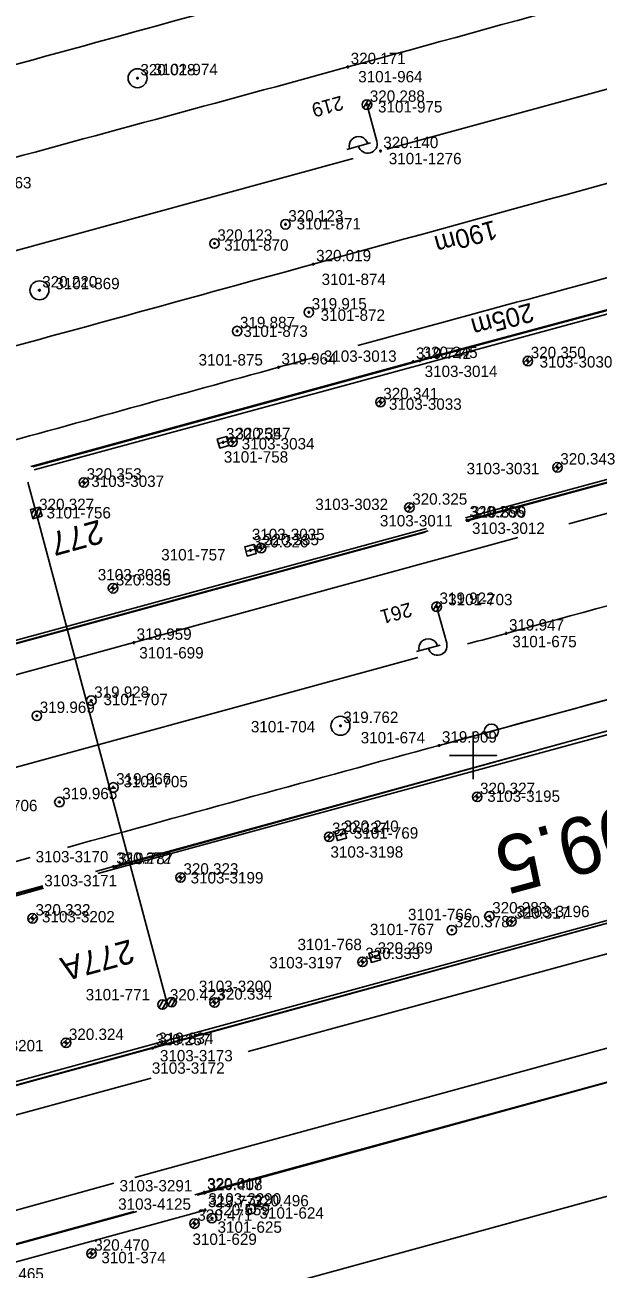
# Model space of a CAD drawing. Extents: x -821875 to -821475, y -1070280 to -1069975.
# Drawn here: x -821573.6 to -821543.4, y -1070227.1 to -1070161.5 of the extents above; entities that cross this region are included whole.
import ezdxf

# ---------------------------------------------------------------- set-up
doc = ezdxf.new("R2010")
doc.units = 0
for name, color, linetype in [('Vrstva 1', 7, 'Continuous'), ('Vrstva 11', 7, 'Continuous'), ('Vrstva 14', 7, 'Continuous'), ('Vrstva 17', 7, 'Continuous'), ('Vrstva 23', 7, 'Continuous'), ('Vrstva 25', 7, 'Continuous'), ('Vrstva 3', 7, 'Continuous'), ('Vrstva 36', 7, 'Continuous'), ('Vrstva 43', 7, 'Continuous'), ('Vrstva 60', 7, 'Continuous'), ('Vrstva 61', 7, 'Continuous'), ('Vrstva 7', 7, 'Continuous')]:
    doc.layers.add(name, color=color, linetype=linetype)

# ---------------------------------------------------------------- blocks, each defined once
blk = doc.blocks.new('BOD')
at = {"layer": 'Vrstva 3'}
for p, q in [((-0.15, 0), (0.15, 0)), ((0, -0.15), (0, 0.15))]:
    blk.add_line(p, q, dxfattribs=at)

msp = doc.modelspace()

# ---------------------------------------------------------------- linework, layer by layer
at = {"layer": 'Vrstva 1'}
for p, q in [((-821530.858, -1070161.578), (-821554.553, -1070168.036)), ((-821556.332, -1070168.522), (-821580.315, -1070175.074)), ((-821532.805, -1070194.296), (-821551.797, -1070199.466)), ((-821552.91, -1070194.831), (-821576.812, -1070201.363)), ((-821500, -1070203.666), (-821567.84, -1070222.249)), ((-821516.436, -1070203.219), (-821561.856, -1070215.603)), ((-821573.357, -1070205.377), (-821602.448, -1070213.353)), ((-821566.968, -1070216.997), (-821586.693, -1070222.375)), ((-821568.932, -1070222.548), (-821610.421, -1070233.913))]:
    msp.add_line(p, q, dxfattribs=at)
for points in [[(-821534.842, -1070185.015), (-821544.956, -1070187.779)], [(-821547.636, -1070188.511), (-821567.889, -1070194.046), (-821588.306, -1070199.621)], [(-821551.25, -1070200), (-821550, -1070200), (-821550, -1070198.75), (-821550, -1070200), (-821548.75, -1070200), (-821550, -1070200), (-821550, -1070201.25)]]:
    msp.add_lwpolyline(points, dxfattribs=at)
for points in [[(-821515.135, -1070116.801), (-821528.933, -1070119.148), (-821545.007, -1070122.191), (-821565.452, -1070126.847), (-821593.911, -1070134.524), (-821616.729, -1070140.773), (-821646.681, -1070148.977), (-821681.98, -1070158.691), (-821694.065, -1070162.076), (-821706.535, -1070165.88), (-821718.507, -1070169.937)], [(-821540.596, -1070125.428), (-821552.18, -1070128.307), (-821562.458, -1070130.974), (-821571.2, -1070133.262), (-821591.887, -1070138.848), (-821628.102, -1070148.713), (-821679.285, -1070162.663)], [(-821540.784, -1070127.42), (-821561.358, -1070134.748), (-821573.215, -1070138.464), (-821586.824, -1070142.326), (-821602.341, -1070146.553), (-821645.37, -1070158.257), (-821677.113, -1070166.912)], [(-821500, -1070129.211), (-821517.764, -1070133.43), (-821543.081, -1070140.233), (-821582.867, -1070151.05), (-821612.032, -1070158.997), (-821647.71, -1070168.745)], [(-821500, -1070134.157), (-821525.227, -1070140.424), (-821545.665, -1070145.962), (-821584.89, -1070156.649), (-821608.863, -1070163.173), (-821645.742, -1070173.228), (-821684.141, -1070183.689)], [(-821500, -1070139.002), (-821505.719, -1070140.359), (-821526.796, -1070145.75), (-821547.362, -1070151.333), (-821583.687, -1070161.245), (-821611.332, -1070168.765), (-821648.899, -1070179.006), (-821680.4, -1070187.609), (-821711.133, -1070195.974)], [(-821500, -1070143.947), (-821500.602, -1070144.082), (-821526.98, -1070150.62), (-821544.477, -1070155.432), (-821558.026, -1070159.151), (-821579.135, -1070164.951), (-821610.376, -1070173.463), (-821647.463, -1070183.595), (-821678.921, -1070192.191), (-821710.276, -1070200.761)], [(-821500, -1070148.817), (-821511.77, -1070151.622), (-821530.609, -1070156.564), (-821556.604, -1070163.701), (-821576.895, -1070169.217), (-821607.294, -1070177.525), (-821643.435, -1070187.343), (-821669.656, -1070194.488)], [(-821500, -1070158.612), (-821502.104, -1070159.113), (-821527.988, -1070165.772), (-821558.427, -1070174.094), (-821579.522, -1070179.891)], [(-821528.694, -1070170.935), (-821535.495, -1070172.784), (-821556.071, -1070178.381)], [(-821558.309, -1070178.995), (-821560.253, -1070179.53), (-821575.821, -1070183.825)], [(-821526.636, -1070187.658), (-821548.257, -1070193.56), (-821550.291, -1070194.116)], [(-821530.049, -1070193.542), (-821532.805, -1070194.296), (-821551.797, -1070199.466), (-821571.39, -1070204.838)], [(-821500, -1070224.932), (-821542.652, -1070236.59), (-821589.48, -1070249.332)]]:
    msp.add_spline(points, degree=3, dxfattribs=at)
at = {"layer": 'Vrstva 11'}
for p, q in [((-821573.469, -1070185.595), (-821573.029, -1070187.208)), ((-821573.108, -1070186.971), (-821573.273, -1070187.261)), ((-821572.854, -1070186.902), (-821573.202, -1070187.515)), ((-821573.029, -1070187.208), (-821566.136, -1070213.06)), ((-821572.784, -1070187.158), (-821572.947, -1070187.444)), ((-821566.328, -1070212.882), (-821566.562, -1070213.293)), ((-821565.843, -1070212.751), (-821566.079, -1070213.163)), ((-821565.687, -1070212.855), (-821565.909, -1070213.243)), ((-821566.171, -1070212.986), (-821566.393, -1070213.375))]:
    msp.add_line(p, q, dxfattribs=at)
msp.add_lwpolyline([(-821572.722, -1070187.383), (-821573.204, -1070187.515), (-821573.336, -1070187.033), (-821572.854, -1070186.901)], close=True, dxfattribs=at)
msp.add_lwpolyline([(-821572.722, -1070187.383), (-821573.204, -1070187.515), (-821573.336, -1070187.033), (-821572.854, -1070186.901), (-821572.722, -1070187.383)], dxfattribs=at)
for centre in [(-821566.377, -1070213.126), (-821566.377, -1070213.126), (-821565.895, -1070212.994), (-821565.895, -1070212.994)]:
    msp.add_circle(centre, 0.25, dxfattribs=at)
at = {"layer": 'Vrstva 14'}
for p, q in [((-821520.255, -1070170.56), (-821573.139, -1070184.936)), ((-821553.163, -1070179.239), (-821573.313, -1070184.766)), ((-821573.206, -1070184.774), (-821552.814, -1070179.193)), ((-821550.394, -1070187.471), (-821522.684, -1070179.932)), ((-821500, -1070187.198), (-821569.776, -1070206.214)), ((-821626.102, -1070208.071), (-821552.45, -1070188.031)), ((-821587.282, -1070220.776), (-821500, -1070196.987)), ((-821572.64, -1070206.994), (-821597.005, -1070213.634)), ((-821530.838, -1070213.903), (-821564.175, -1070223.021)), ((-821530.539, -1070213.83), (-821564.154, -1070223.059)), ((-821564.175, -1070223.021), (-821564.669, -1070223.157)), ((-821564.154, -1070223.059), (-821564.546, -1070223.166)), ((-821567.723, -1070224.034), (-821612.131, -1070236.166)), ((-821567.873, -1070224.036), (-821612.125, -1070236.188))]:
    msp.add_line(p, q, dxfattribs=at)
for points in [[(-821553.163, -1070179.239), (-821523.624, -1070171.317)], [(-821523.662, -1070171.348), (-821552.814, -1070179.193)], [(-821550.335, -1070187.597), (-821522.393, -1070180.046)], [(-821522.413, -1070180.061), (-821550.25, -1070187.611)], [(-821593.697, -1070199.421), (-821552.369, -1070188.152)], [(-821552.524, -1070188.23), (-821593.592, -1070199.416)], [(-821524.974, -1070193.772), (-821568.963, -1070205.855)], [(-821525.05, -1070193.765), (-821568.859, -1070205.873)], [(-821500, -1070197.101), (-821519.046, -1070202.296), (-821566.74, -1070215.352), (-821587.58, -1070221.064)], [(-821587.424, -1070221.035), (-821566.902, -1070215.424), (-821519.308, -1070202.358), (-821500, -1070197.087)], [(-821568.963, -1070205.855), (-821569.898, -1070206.112)], [(-821572.675, -1070206.874), (-821597.33, -1070213.642)], [(-821572.691, -1070206.915), (-821596.666, -1070213.434)]]:
    msp.add_lwpolyline(points, dxfattribs=at)
at = {"layer": 'Vrstva 17'}
msp.add_lwpolyline([(-821561.818, -1070228.402), (-821540.931, -1070222.686), (-821538.779, -1070230.644), (-821559.821, -1070236.162), (-821561.818, -1070228.402)], dxfattribs=at)
at = {"layer": 'Vrstva 23'}
msp.add_lwpolyline([(-821579.481, -1070228.171), (-821564.133, -1070223.955)], dxfattribs=at)
at = {"layer": 'Vrstva 25'}
for p, q in [((-821555.538, -1070165.445), (-821555.776, -1070165.86)), ((-821555.385, -1070165.554), (-821555.603, -1070165.935)), ((-821555.531, -1070165.928), (-821555.071, -1070167.616)), ((-821555.408, -1070167.708), (-821556.662, -1070168.05)), ((-821559.916, -1070171.997), (-821559.866, -1070171.997)), ((-821563.659, -1070173.009), (-821563.609, -1070173.009)), ((-821558.683, -1070176.633), (-821558.633, -1070176.633)), ((-821562.466, -1070177.622), (-821562.416, -1070177.622)), ((-821551.864, -1070191.911), (-821552.1, -1070192.326)), ((-821551.71, -1070192.02), (-821551.927, -1070192.401)), ((-821551.855, -1070192.394), (-821551.394, -1070194.082)), ((-821551.731, -1070194.174), (-821552.985, -1070194.517)), ((-821570.152, -1070197.103), (-821570.102, -1070197.103)), ((-821573.02, -1070197.904), (-821572.97, -1070197.904)), ((-821568.992, -1070201.676), (-821568.942, -1070201.676)), ((-821571.835, -1070202.448), (-821571.785, -1070202.448)), ((-821549.168, -1070208.47), (-821549.118, -1070208.47)), ((-821551.149, -1070209.203), (-821551.099, -1070209.203)), ((-821561.741, -1070223.912), (-821561.691, -1070223.912)), ((-821563.792, -1070224.385), (-821563.742, -1070224.385))]:
    msp.add_line(p, q, dxfattribs=at)
for centre in [(-821555.596, -1070165.687), (-821555.596, -1070165.687), (-821559.891, -1070171.997), (-821563.634, -1070173.009), (-821558.658, -1070176.633), (-821562.441, -1070177.622), (-821551.921, -1070192.153), (-821551.921, -1070192.153), (-821570.127, -1070197.103), (-821572.995, -1070197.904), (-821568.967, -1070201.676), (-821571.81, -1070202.448), (-821549.143, -1070208.47), (-821551.124, -1070209.203), (-821561.716, -1070223.912), (-821563.767, -1070224.385)]:
    msp.add_circle(centre, 0.25, dxfattribs=at)
for centre, start, end in [((-821556.037, -1070167.874), 14.53609, 195.94123), ((-821555.553, -1070167.748), 195.23866, 15.23866), ((-821552.359, -1070194.34), 14.59593, 196.00107), ((-821551.876, -1070194.214), 195.2985, 15.2985)]:
    msp.add_arc(centre, 0.5, start, end, dxfattribs=at)
at = {"layer": 'Vrstva 36'}
for p, q in [((-821547.344, -1070179.294), (-821547.02, -1070178.971)), ((-821547.214, -1070179.429), (-821546.886, -1070179.102)), ((-821555.116, -1070181.458), (-821554.794, -1070181.135)), ((-821554.986, -1070181.593), (-821554.659, -1070181.266)), ((-821562.91, -1070183.557), (-821562.588, -1070183.234)), ((-821562.78, -1070183.692), (-821562.453, -1070183.364)), ((-821545.784, -1070184.899), (-821545.462, -1070184.576)), ((-821545.654, -1070185.034), (-821545.327, -1070184.706)), ((-821570.752, -1070185.694), (-821570.43, -1070185.371)), ((-821570.622, -1070185.829), (-821570.295, -1070185.502)), ((-821553.59, -1070187.015), (-821553.268, -1070186.692)), ((-821553.46, -1070187.15), (-821553.133, -1070186.822)), ((-821561.408, -1070189.153), (-821561.086, -1070188.83)), ((-821561.278, -1070189.288), (-821560.951, -1070188.96)), ((-821569.212, -1070191.274), (-821568.89, -1070190.951)), ((-821569.082, -1070191.409), (-821568.755, -1070191.082)), ((-821550.016, -1070202.271), (-821549.692, -1070201.948)), ((-821549.886, -1070202.406), (-821549.558, -1070202.078)), ((-821557.82, -1070204.375), (-821557.498, -1070204.052)), ((-821557.69, -1070204.51), (-821557.363, -1070204.182)), ((-821565.652, -1070206.517), (-821565.33, -1070206.194)), ((-821565.522, -1070206.652), (-821565.195, -1070206.324)), ((-821573.452, -1070208.673), (-821573.128, -1070208.35)), ((-821573.322, -1070208.808), (-821572.994, -1070208.48)), ((-821548.216, -1070208.835), (-821547.892, -1070208.512)), ((-821548.086, -1070208.97), (-821547.758, -1070208.642)), ((-821556.064, -1070210.967), (-821555.74, -1070210.644)), ((-821555.934, -1070211.102), (-821555.606, -1070210.774)), ((-821563.862, -1070213.108), (-821563.538, -1070212.785)), ((-821563.732, -1070213.243), (-821563.404, -1070212.916)), ((-821571.69, -1070215.233), (-821571.368, -1070214.91)), ((-821571.56, -1070215.368), (-821571.233, -1070215.04)), ((-821564.918, -1070224.763), (-821564.594, -1070224.44)), ((-821564.788, -1070224.898), (-821564.46, -1070224.57)), ((-821570.352, -1070226.34), (-821570.03, -1070226.017)), ((-821570.222, -1070226.475), (-821569.895, -1070226.148))]:
    msp.add_line(p, q, dxfattribs=at)
for centre in [(-821547.113, -1070179.202), (-821554.886, -1070181.366), (-821562.68, -1070183.465), (-821545.554, -1070184.807), (-821570.522, -1070185.602), (-821553.36, -1070186.923), (-821561.178, -1070189.061), (-821568.982, -1070191.182), (-821549.785, -1070202.179), (-821557.59, -1070204.283), (-821565.422, -1070206.425), (-821573.221, -1070208.581), (-821547.985, -1070208.743), (-821555.833, -1070210.875), (-821563.631, -1070213.016), (-821571.46, -1070215.141), (-821564.687, -1070224.671), (-821570.122, -1070226.248)]:
    msp.add_circle(centre, 0.25, dxfattribs=at)
at = {"layer": 'Vrstva 43'}
for points in [[(-821562.936, -1070183.42), (-821562.87, -1070183.66), (-821563.351, -1070183.793), (-821563.484, -1070183.312), (-821563.003, -1070183.179), (-821562.936, -1070183.42), (-821563.418, -1070183.552)], [(-821561.495, -1070189.111), (-821561.429, -1070189.352), (-821561.911, -1070189.484), (-821562.043, -1070189.002), (-821561.561, -1070188.87), (-821561.495, -1070189.111), (-821561.977, -1070189.243)], [(-821556.734, -1070204.105), (-821556.668, -1070204.346), (-821557.15, -1070204.478), (-821557.282, -1070203.996), (-821556.8, -1070203.864), (-821556.734, -1070204.105), (-821557.216, -1070204.237)], [(-821554.941, -1070210.526), (-821554.875, -1070210.768), (-821555.358, -1070210.899), (-821555.489, -1070210.416), (-821555.006, -1070210.285), (-821554.941, -1070210.526), (-821555.423, -1070210.658)]]:
    msp.add_lwpolyline(points, dxfattribs=at)
for centre in [(-821567.69, -1070164.294), (-821572.863, -1070175.473), (-821556.993, -1070198.431)]:
    msp.add_circle(centre, 0.5, dxfattribs=at)
at = {"layer": 'Vrstva 7'}
msp.add_circle((-821549.036, -1070198.714), 0.375, dxfattribs=at)

# ---------------------------------------------------------------- block references
at = {"layer": 'Vrstva 60', "xscale": 0.5, "yscale": 0.5}
for p in [(-821556.604, -1070163.701), (-821567.69, -1070164.294), (-821555.596, -1070165.687), (-821554.885, -1070168.127), (-821559.891, -1070171.997), (-821563.634, -1070173.009), (-821558.427, -1070174.094), (-821572.863, -1070175.473), (-821558.658, -1070176.633), (-821562.441, -1070177.622), (-821560.253, -1070179.53), (-821553.163, -1070179.239), (-821552.814, -1070179.193), (-821547.113, -1070179.202), (-821554.886, -1070181.366), (-821563.177, -1070183.486), (-821562.68, -1070183.465), (-821545.554, -1070184.807), (-821570.522, -1070185.602), (-821573.029, -1070187.208), (-821553.36, -1070186.923), (-821550.335, -1070187.597), (-821550.25, -1070187.611), (-821561.736, -1070189.177), (-821561.178, -1070189.061), (-821568.982, -1070191.182), (-821551.921, -1070192.153), (-821548.257, -1070193.56), (-821567.889, -1070194.046), (-821570.127, -1070197.103), (-821572.995, -1070197.904), (-821556.993, -1070198.431), (-821551.797, -1070199.466), (-821568.967, -1070201.676), (-821571.81, -1070202.448), (-821549.785, -1070202.179), (-821557.59, -1070204.283), (-821556.975, -1070204.171), (-821568.963, -1070205.855), (-821568.859, -1070205.873), (-821565.422, -1070206.425), (-821573.221, -1070208.581), (-821549.143, -1070208.47), (-821547.985, -1070208.743), (-821551.124, -1070209.203), (-821555.833, -1070210.875), (-821555.182, -1070210.592), (-821563.631, -1070213.016), (-821566.136, -1070213.06), (-821571.46, -1070215.141), (-821566.902, -1070215.424), (-821566.74, -1070215.352), (-821564.175, -1070223.021), (-821564.154, -1070223.059), (-821564.133, -1070223.955), (-821561.716, -1070223.912), (-821564.687, -1070224.671), (-821563.767, -1070224.385), (-821570.122, -1070226.248)]:
    msp.add_blockref('BOD', p, dxfattribs=at)

# ---------------------------------------------------------------- texts
at = {"layer": 'Vrstva 1'}
for s, rotation, p in [('190m', 195.2946, (-821548.896, -1070171.763)), ('205m', 195.23754, (-821546.965, -1070176.121))]:
    msp.add_text(s, height=1, rotation=rotation, dxfattribs=at).set_placement(p)
at = {"layer": 'Vrstva 11'}
for s, rotation, p in [('277', 195.35197, (-821569.71, -1070187.55)), ('277A', 195.26368, (-821568.08, -1070209.672))]:
    msp.add_text(s, height=1.25, rotation=rotation, dxfattribs=at).set_placement(p)
at = {"layer": 'Vrstva 25'}
for s, rotation, p in [('219', 195.23857, (-821556.961, -1070165.205)), ('261', 195.29857, (-821553.344, -1070191.916))]:
    msp.add_text(s, height=0.75, rotation=rotation, dxfattribs=at).set_placement(p)
at = {"layer": 'Vrstva 60'}
for s, p in [('3101-974', (-821566.853, -1070164.131)), ('3101-964', (-821556.056, -1070164.512)), ('3101-975', (-821555.012, -1070166.1)), ('3101-1276', (-821554.446, -1070168.83)), ('3101-963', (-821576.673, -1070170.1)), ('3101-871', (-821559.307, -1070172.267)), ('3101-870', (-821563.123, -1070173.387)), ('3101-869', (-821572.026, -1070175.418)), ('3101-874', (-821557.988, -1070175.194)), ('3101-872', (-821558.038, -1070177.083)), ('3101-873', (-821562.11, -1070177.928)), ('3101-875', (-821564.474, -1070179.439)), ('3103-3013', (-821557.869, -1070179.244)), ('3103-3014', (-821552.557, -1070180.045)), ('3103-3030', (-821546.497, -1070179.546)), ('3103-3033', (-821554.439, -1070181.773)), ('3103-3034', (-821562.199, -1070183.862)), ('3101-758', (-821563.141, -1070184.557)), ('3103-3031', (-821550.344, -1070185.172)), ('3103-3037', (-821570.128, -1070185.839)), ('3103-3032', (-821558.32, -1070187.055)), ('3101-756', (-821572.487, -1070187.499)), ('3103-3011', (-821554.914, -1070187.92)), ('3103-3035', (-821561.664, -1070188.642)), ('3103-3012', (-821550.058, -1070188.316)), ('3101-757', (-821566.442, -1070189.712)), ('3103-3036', (-821569.787, -1070190.764)), ('3101-703', (-821551.316, -1070192.078)), ('3101-675', (-821547.932, -1070194.29)), ('3101-699', (-821567.598, -1070194.882)), ('3101-707', (-821569.486, -1070197.343)), ('3101-704', (-821561.716, -1070198.776)), ('3101-674', (-821555.925, -1070199.356)), ('3101-705', (-821568.431, -1070201.671)), ('3103-3195', (-821549.256, -1070202.439)), ('3101-706', (-821576.358, -1070202.933)), ('3101-769', (-821556.284, -1070204.378)), ('3103-3170', (-821573.064, -1070205.629)), ('3103-3198', (-821557.521, -1070205.382)), ('3103-3171', (-821572.608, -1070206.891)), ('3103-3199', (-821564.893, -1070206.74)), ('3103-3202', (-821572.728, -1070208.793)), ('3101-766', (-821553.434, -1070208.676)), ('3103-3196', (-821547.7, -1070208.517)), ('3101-767', (-821555.441, -1070209.464)), ('3101-768', (-821559.256, -1070210.257)), ('3103-3197', (-821560.746, -1070211.217)), ('3101-771', (-821570.422, -1070212.903)), ('3103-3200', (-821564.459, -1070212.464)), ('3103-3201', (-821576.485, -1070215.591)), ('3103-3173', (-821566.51, -1070216.119)), ('3103-3172', (-821566.936, -1070216.771)), ('3103-3291', (-821568.64, -1070222.974)), ('3103-4125', (-821568.711, -1070223.941)), ('3103-3290', (-821563.956, -1070223.669)), ('3101-624', (-821561.261, -1070224.41)), ('3101-625', (-821563.473, -1070225.155)), ('3101-629', (-821564.794, -1070225.794)), ('3101-374', (-821569.597, -1070226.76))]:
    msp.add_text(s, height=0.6, dxfattribs=at).set_placement(p)
at = {"layer": 'Vrstva 61'}
for s, p in [('320.171', (-821556.454, -1070163.551)), ('320.028', (-821567.54, -1070164.144)), ('320.288', (-821555.446, -1070165.537)), ('320.140', (-821554.735, -1070167.977)), ('320.123', (-821559.741, -1070171.847)), ('320.123', (-821563.484, -1070172.859)), ('320.019', (-821558.277, -1070173.944)), ('320.220', (-821572.713, -1070175.323)), ('319.915', (-821558.508, -1070176.483)), ('319.887', (-821562.291, -1070177.472)), ('319.964', (-821560.103, -1070179.38)), ('319.742', (-821553.013, -1070179.089)), ('320.245', (-821552.664, -1070179.043)), ('320.350', (-821546.963, -1070179.052)), ('320.341', (-821554.736, -1070181.216)), ('320.255', (-821563.027, -1070183.336)), ('320.347', (-821562.53, -1070183.315)), ('320.343', (-821545.404, -1070184.657)), ('320.353', (-821570.372, -1070185.452)), ('320.327', (-821572.879, -1070187.058)), ('320.325', (-821553.21, -1070186.773)), ('320.266', (-821550.185, -1070187.447)), ('319.899', (-821550.1, -1070187.461)), ('320.326', (-821561.586, -1070189.027)), ('320.335', (-821561.028, -1070188.911)), ('320.335', (-821568.832, -1070191.032)), ('319.922', (-821551.771, -1070192.003)), ('319.959', (-821567.739, -1070193.896)), ('319.947', (-821548.107, -1070193.41)), ('319.928', (-821569.977, -1070196.953)), ('319.969', (-821572.845, -1070197.754)), ('319.762', (-821556.843, -1070198.281)), ('319.909', (-821551.647, -1070199.316)), ('319.966', (-821568.817, -1070201.526)), ('319.965', (-821571.66, -1070202.298)), ('320.327', (-821549.635, -1070202.029)), ('320.337', (-821557.44, -1070204.133)), ('320.240', (-821556.825, -1070204.021)), ('320.272', (-821568.813, -1070205.705)), ('319.787', (-821568.709, -1070205.723)), ('320.323', (-821565.272, -1070206.275)), ('320.283', (-821548.993, -1070208.32)), ('320.332', (-821573.071, -1070208.431)), ('320.317', (-821547.835, -1070208.593)), ('320.378', (-821550.974, -1070209.053)), ('320.333', (-821555.683, -1070210.725)), ('320.269', (-821555.032, -1070210.442)), ('320.423', (-821565.986, -1070212.91)), ('320.334', (-821563.481, -1070212.866)), ('320.324', (-821571.31, -1070214.991)), ('320.257', (-821566.752, -1070215.274)), ('319.834', (-821566.59, -1070215.202)), ('320.017', (-821564.025, -1070222.871)), ('320.408', (-821564.004, -1070222.909)), ('323.772', (-821563.983, -1070223.805)), ('320.496', (-821561.566, -1070223.762)), ('320.471', (-821564.537, -1070224.521)), ('320.559', (-821563.617, -1070224.235)), ('320.470', (-821569.972, -1070226.098)), ('320.465', (-821575.531, -1070227.616))]:
    msp.add_text(s, height=0.6, dxfattribs=at).set_placement(p)
at = {"layer": 'Vrstva 7'}
msp.add_text('109.5', height=3, rotation=195.22802, dxfattribs=at).set_placement((-821539.371, -1070201.834))

doc.saveas('drawing.dxf')
